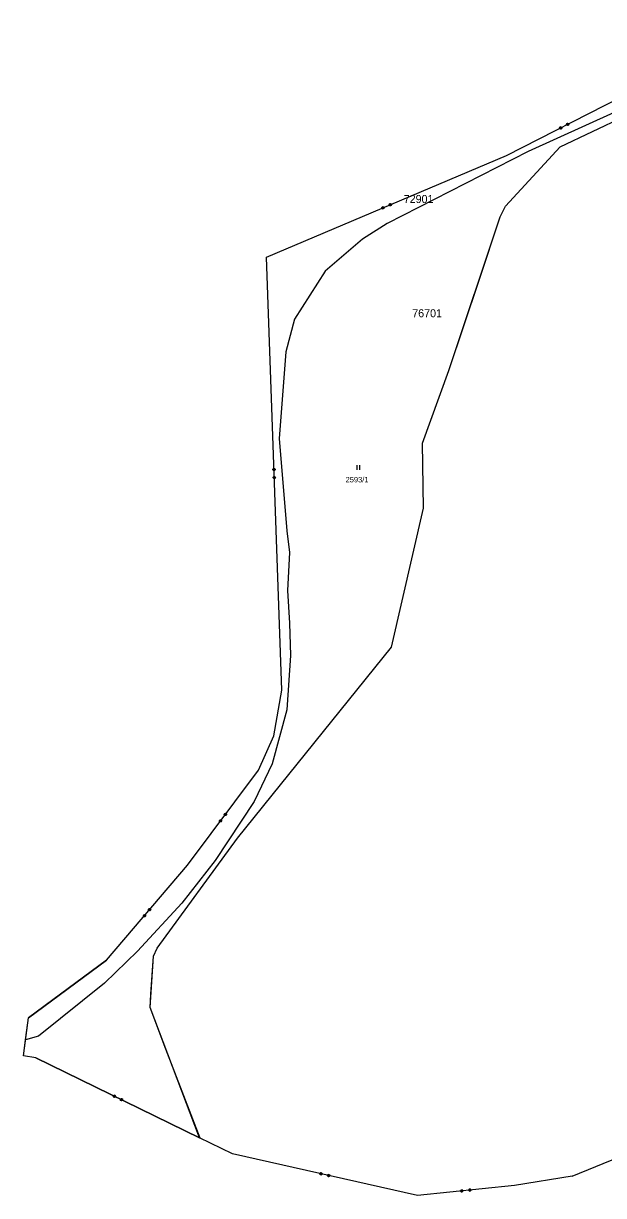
# Model space of a CAD drawing. Extents: x -760611 to -758411, y -1176479 to -1174807.
# Drawn here: x -760611.1 to -760429.8, y -1176478.9 to -1176112.8 of the extents above; entities that cross this region are included whole.
import ezdxf

# ---------------------------------------------------------------- set-up
doc = ezdxf.new("R2010")
doc.units = 0
for name, color, linetype in [('1', 7, 'Continuous'), ('11', 7, 'Continuous'), ('2', 7, 'Continuous'), ('3', 7, 'Continuous')]:
    doc.layers.add(name, color=color, linetype=linetype)

msp = doc.modelspace()

# ---------------------------------------------------------------- linework, layer by layer
at = {"layer": '1'}
for p, q in [((-760460.11, -1176154.07), (-760424.14, -1176135.79)), ((-760443.32, -1176151.33), (-760423.07, -1176141.77)), ((-760460.38, -1176169.87), (-760443.32, -1176151.33)), ((-760535.16, -1176185.8), (-760460.11, -1176154.07)), ((-760462.1, -1176173.26), (-760460.38, -1176169.87)), ((-760478.12, -1176221.24), (-760462.1, -1176173.26)), ((-760530.31, -1176321.04), (-760535.16, -1176185.8)), ((-760486.4, -1176243.86), (-760478.12, -1176221.24)), ((-760486.07, -1176264.19), (-760486.4, -1176243.86)), ((-760496.02, -1176307.61), (-760486.07, -1176264.19)), ((-760544.14, -1176367.23), (-760496.02, -1176307.61)), ((-760532.8, -1176335.28), (-760530.31, -1176321.04)), ((-760537.67, -1176346.05), (-760532.8, -1176335.28)), ((-760559.85, -1176375.71), (-760537.67, -1176346.05)), ((-760569.34, -1176401.64), (-760544.14, -1176367.23)), ((-760585.17, -1176405.4), (-760559.85, -1176375.71)), ((-760570.49, -1176404.12), (-760569.34, -1176401.64)), ((-760585.17, -1176405.4), (-760601.92, -1176417.76)), ((-760571.54, -1176420.09), (-760570.49, -1176404.12)), ((-760601.92, -1176417.76), (-760609.56, -1176423.39)), ((-760556.03, -1176460.82), (-760571.54, -1176420.09)), ((-760611.11, -1176435.21), (-760609.56, -1176423.39)), ((-760607.21, -1176435.9), (-760611.11, -1176435.21)), ((-760607.21, -1176435.9), (-760556.03, -1176460.82)), ((-760545.74, -1176465.83), (-760556.03, -1176460.82)), ((-760487.96, -1176478.86), (-760545.74, -1176465.83)), ((-760439.57, -1176472.8), (-760424.82, -1176466.77)), ((-760457.63, -1176475.7), (-760487.96, -1176478.86)), ((-760439.57, -1176472.8), (-760457.63, -1176475.7))]:
    msp.add_line(p, q, dxfattribs=at)
for points in [[(-760443.22, -1176145.13), (-760442.97, -1176145.21), (-760442.85, -1176145.45), (-760442.93, -1176145.71), (-760443.17, -1176145.83), (-760443.43, -1176145.75), (-760443.55, -1176145.51), (-760443.46, -1176145.25), (-760443.22, -1176145.13), (-760443.21, -1176145.17), (-760443.43, -1176145.28), (-760443.46, -1176145.39), (-760443.11, -1176145.2), (-760443, -1176145.24), (-760443.5, -1176145.49), (-760443.46, -1176145.56), (-760442.96, -1176145.31), (-760442.93, -1176145.38), (-760443.43, -1176145.64), (-760443.39, -1176145.71), (-760442.89, -1176145.45), (-760442.93, -1176145.56), (-760443.28, -1176145.74), (-760443.18, -1176145.78), (-760442.96, -1176145.67)], [(-760440.99, -1176144), (-760440.74, -1176144.08), (-760440.62, -1176144.32), (-760440.7, -1176144.58), (-760440.94, -1176144.7), (-760441.2, -1176144.62), (-760441.32, -1176144.37), (-760441.24, -1176144.12), (-760440.99, -1176144), (-760441, -1176144.05), (-760441.22, -1176144.16), (-760441.25, -1176144.26), (-760440.9, -1176144.08), (-760440.79, -1176144.12), (-760441.29, -1176144.37), (-760441.25, -1176144.44), (-760440.75, -1176144.19), (-760440.72, -1176144.26), (-760441.22, -1176144.51), (-760441.18, -1176144.58), (-760440.68, -1176144.33), (-760440.71, -1176144.44), (-760441.07, -1176144.62), (-760440.96, -1176144.65), (-760440.75, -1176144.55)], [(-760498.75, -1176170.06), (-760498.5, -1176170.16), (-760498.39, -1176170.41), (-760498.49, -1176170.66), (-760498.74, -1176170.76), (-760498.99, -1176170.66), (-760499.09, -1176170.41), (-760498.99, -1176170.16), (-760498.75, -1176170.06), (-760498.74, -1176170.1), (-760498.96, -1176170.19), (-760499, -1176170.3), (-760498.63, -1176170.14), (-760498.53, -1176170.18), (-760499.04, -1176170.4), (-760499.01, -1176170.47), (-760498.5, -1176170.26), (-760498.47, -1176170.33), (-760498.98, -1176170.55), (-760498.95, -1176170.62), (-760498.44, -1176170.4), (-760498.48, -1176170.51), (-760498.85, -1176170.66), (-760498.74, -1176170.71), (-760498.52, -1176170.61)], [(-760496.44, -1176169.08), (-760496.19, -1176169.18), (-760496.09, -1176169.43), (-760496.19, -1176169.68), (-760496.44, -1176169.79), (-760496.69, -1176169.69), (-760496.79, -1176169.44), (-760496.69, -1176169.19), (-760496.44, -1176169.08), (-760496.45, -1176169.13), (-760496.68, -1176169.23), (-760496.72, -1176169.33), (-760496.35, -1176169.17), (-760496.24, -1176169.22), (-760496.76, -1176169.44), (-760496.73, -1176169.51), (-760496.21, -1176169.29), (-760496.18, -1176169.36), (-760496.7, -1176169.58), (-760496.67, -1176169.66), (-760496.15, -1176169.44), (-760496.19, -1176169.54), (-760496.56, -1176169.7), (-760496.46, -1176169.74), (-760496.24, -1176169.65)], [(-760533.11, -1176252), (-760532.92, -1176251.81), (-760532.65, -1176251.8), (-760532.46, -1176251.98), (-760532.45, -1176252.25), (-760532.63, -1176252.45), (-760532.9, -1176252.46), (-760533.1, -1176252.27), (-760533.11, -1176252), (-760533.07, -1176252.03), (-760533.06, -1176252.27), (-760532.97, -1176252.35), (-760532.99, -1176251.95), (-760532.91, -1176251.87), (-760532.89, -1176252.42), (-760532.81, -1176252.42), (-760532.83, -1176251.86), (-760532.75, -1176251.86), (-760532.73, -1176252.42), (-760532.65, -1176252.42), (-760532.67, -1176251.86), (-760532.59, -1176251.93), (-760532.57, -1176252.33), (-760532.5, -1176252.25), (-760532.51, -1176252.01)], [(-760533.02, -1176254.5), (-760532.83, -1176254.3), (-760532.56, -1176254.29), (-760532.37, -1176254.48), (-760532.36, -1176254.75), (-760532.54, -1176254.94), (-760532.81, -1176254.95), (-760533.01, -1176254.77), (-760533.02, -1176254.5), (-760532.98, -1176254.51), (-760532.97, -1176254.75), (-760532.88, -1176254.83), (-760532.9, -1176254.43), (-760532.82, -1176254.34), (-760532.8, -1176254.9), (-760532.72, -1176254.9), (-760532.74, -1176254.34), (-760532.66, -1176254.34), (-760532.64, -1176254.9), (-760532.56, -1176254.89), (-760532.58, -1176254.34), (-760532.5, -1176254.41), (-760532.48, -1176254.81), (-760532.41, -1176254.73), (-760532.42, -1176254.49)], [(-760549.66, -1176361.55), (-760549.39, -1176361.51), (-760549.17, -1176361.67), (-760549.14, -1176361.93), (-760549.3, -1176362.15), (-760549.56, -1176362.19), (-760549.78, -1176362.03), (-760549.82, -1176361.76), (-760549.66, -1176361.55), (-760549.63, -1176361.58), (-760549.77, -1176361.77), (-760549.76, -1176361.88), (-760549.52, -1176361.56), (-760549.41, -1176361.55), (-760549.74, -1176361.99), (-760549.68, -1176362.04), (-760549.34, -1176361.59), (-760549.28, -1176361.64), (-760549.61, -1176362.09), (-760549.55, -1176362.14), (-760549.21, -1176361.69), (-760549.2, -1176361.8), (-760549.44, -1176362.12), (-760549.33, -1176362.1), (-760549.18, -1176361.91)], [(-760548.16, -1176359.54), (-760547.89, -1176359.5), (-760547.68, -1176359.67), (-760547.64, -1176359.93), (-760547.8, -1176360.15), (-760548.07, -1176360.19), (-760548.28, -1176360.03), (-760548.32, -1176359.76), (-760548.16, -1176359.54), (-760548.15, -1176359.59), (-760548.29, -1176359.78), (-760548.27, -1176359.9), (-760548.03, -1176359.57), (-760547.92, -1176359.56), (-760548.26, -1176360.01), (-760548.19, -1176360.06), (-760547.86, -1176359.61), (-760547.79, -1176359.65), (-760548.13, -1176360.1), (-760548.07, -1176360.15), (-760547.73, -1176359.7), (-760547.71, -1176359.81), (-760547.95, -1176360.13), (-760547.84, -1176360.12), (-760547.7, -1176359.93)], [(-760573.45, -1176391.16), (-760573.18, -1176391.14), (-760572.97, -1176391.32), (-760572.95, -1176391.58), (-760573.13, -1176391.79), (-760573.4, -1176391.81), (-760573.6, -1176391.64), (-760573.62, -1176391.37), (-760573.45, -1176391.16), (-760573.42, -1176391.2), (-760573.58, -1176391.38), (-760573.57, -1176391.49), (-760573.31, -1176391.19), (-760573.2, -1176391.18), (-760573.56, -1176391.6), (-760573.5, -1176391.66), (-760573.14, -1176391.23), (-760573.08, -1176391.28), (-760573.44, -1176391.71), (-760573.38, -1176391.76), (-760573.02, -1176391.33), (-760573.01, -1176391.45), (-760573.27, -1176391.75), (-760573.15, -1176391.74), (-760573, -1176391.56)], [(-760571.83, -1176389.26), (-760571.56, -1176389.24), (-760571.35, -1176389.41), (-760571.33, -1176389.68), (-760571.51, -1176389.89), (-760571.77, -1176389.91), (-760571.98, -1176389.73), (-760572, -1176389.46), (-760571.83, -1176389.26), (-760571.82, -1176389.31), (-760571.97, -1176389.49), (-760571.96, -1176389.6), (-760571.7, -1176389.3), (-760571.59, -1176389.29), (-760571.95, -1176389.72), (-760571.89, -1176389.77), (-760571.53, -1176389.34), (-760571.47, -1176389.39), (-760571.83, -1176389.82), (-760571.77, -1176389.87), (-760571.41, -1176389.45), (-760571.4, -1176389.56), (-760571.66, -1176389.86), (-760571.54, -1176389.85), (-760571.39, -1176389.67)], [(-760582.44, -1176447.6), (-760582.35, -1176447.86), (-760582.47, -1176448.1), (-760582.73, -1176448.19), (-760582.97, -1176448.07), (-760583.06, -1176447.82), (-760582.94, -1176447.57), (-760582.68, -1176447.49), (-760582.44, -1176447.6), (-760582.47, -1176447.64), (-760582.68, -1176447.53), (-760582.79, -1176447.57), (-760582.43, -1176447.74), (-760582.39, -1176447.85), (-760582.9, -1176447.6), (-760582.93, -1176447.68), (-760582.43, -1176447.92), (-760582.46, -1176447.99), (-760582.97, -1176447.75), (-760583, -1176447.82), (-760582.5, -1176448.07), (-760582.61, -1176448.1), (-760582.97, -1176447.93), (-760582.93, -1176448.03), (-760582.71, -1176448.14)], [(-760580.19, -1176448.7), (-760580.11, -1176448.95), (-760580.22, -1176449.2), (-760580.48, -1176449.28), (-760580.72, -1176449.16), (-760580.81, -1176448.91), (-760580.69, -1176448.67), (-760580.44, -1176448.58), (-760580.19, -1176448.7), (-760580.24, -1176448.72), (-760580.45, -1176448.62), (-760580.56, -1176448.65), (-760580.2, -1176448.83), (-760580.16, -1176448.94), (-760580.67, -1176448.69), (-760580.7, -1176448.76), (-760580.2, -1176449.01), (-760580.23, -1176449.08), (-760580.74, -1176448.83), (-760580.77, -1176448.91), (-760580.27, -1176449.15), (-760580.38, -1176449.19), (-760580.74, -1176449.01), (-760580.7, -1176449.12), (-760580.48, -1176449.22)], [(-760518.32, -1176472.34), (-760518.46, -1176472.12), (-760518.4, -1176471.85), (-760518.17, -1176471.71), (-760517.91, -1176471.77), (-760517.77, -1176472), (-760517.82, -1176472.26), (-760518.05, -1176472.4), (-760518.32, -1176472.34), (-760518.28, -1176472.31), (-760518.04, -1176472.36), (-760517.95, -1176472.3), (-760518.34, -1176472.21), (-760518.4, -1176472.12), (-760517.85, -1176472.24), (-760517.83, -1176472.16), (-760518.38, -1176472.04), (-760518.36, -1176471.96), (-760517.82, -1176472.09), (-760517.8, -1176472.01), (-760518.35, -1176471.89), (-760518.25, -1176471.82), (-760517.86, -1176471.91), (-760517.92, -1176471.82), (-760518.15, -1176471.76)], [(-760515.88, -1176472.89), (-760516.02, -1176472.67), (-760515.96, -1176472.4), (-760515.73, -1176472.26), (-760515.47, -1176472.32), (-760515.33, -1176472.54), (-760515.39, -1176472.81), (-760515.61, -1176472.95), (-760515.88, -1176472.89), (-760515.86, -1176472.86), (-760515.62, -1176472.91), (-760515.53, -1176472.85), (-760515.92, -1176472.76), (-760515.98, -1176472.66), (-760515.43, -1176472.79), (-760515.41, -1176472.71), (-760515.96, -1176472.59), (-760515.94, -1176472.51), (-760515.4, -1176472.63), (-760515.38, -1176472.55), (-760515.93, -1176472.43), (-760515.83, -1176472.37), (-760515.44, -1176472.46), (-760515.5, -1176472.36), (-760515.73, -1176472.31)], [(-760474.18, -1176477.75), (-760474.39, -1176477.58), (-760474.42, -1176477.31), (-760474.25, -1176477.1), (-760473.98, -1176477.07), (-760473.77, -1176477.24), (-760473.75, -1176477.51), (-760473.92, -1176477.72), (-760474.18, -1176477.75), (-760474.16, -1176477.7), (-760473.92, -1176477.68), (-760473.85, -1176477.59), (-760474.25, -1176477.63), (-760474.33, -1176477.56), (-760473.78, -1176477.5), (-760473.79, -1176477.42), (-760474.34, -1176477.48), (-760474.35, -1176477.4), (-760473.79, -1176477.34), (-760473.8, -1176477.26), (-760474.36, -1176477.32), (-760474.29, -1176477.23), (-760473.89, -1176477.19), (-760473.98, -1176477.12), (-760474.22, -1176477.15)], [(-760471.7, -1176477.49), (-760471.91, -1176477.32), (-760471.93, -1176477.05), (-760471.76, -1176476.84), (-760471.5, -1176476.81), (-760471.29, -1176476.98), (-760471.26, -1176477.25), (-760471.43, -1176477.46), (-760471.7, -1176477.49), (-760471.69, -1176477.45), (-760471.45, -1176477.42), (-760471.38, -1176477.33), (-760471.78, -1176477.38), (-760471.87, -1176477.3), (-760471.31, -1176477.25), (-760471.32, -1176477.17), (-760471.88, -1176477.22), (-760471.88, -1176477.15), (-760471.33, -1176477.09), (-760471.34, -1176477.01), (-760471.89, -1176477.07), (-760471.82, -1176476.98), (-760471.42, -1176476.94), (-760471.51, -1176476.87), (-760471.75, -1176476.89)]]:
    msp.add_lwpolyline(points, dxfattribs=at)
at = {"layer": '11'}
msp.add_line((-760606.43, -1176429.08), (-760610.45, -1176430.21), dxfattribs=at)
for points in [[(-760610.45, -1176430.21), (-760609.56, -1176423.39), (-760585.17, -1176405.4), (-760559.85, -1176375.71), (-760537.67, -1176346.05), (-760532.8, -1176335.28), (-760530.31, -1176321.04), (-760535.16, -1176185.8), (-760460.11, -1176154.07), (-760424.14, -1176135.79), (-760397.95, -1176122.89), (-760368.61, -1176112.84), (-760363.38, -1176119.64)], [(-760555.89, -1176460.89), (-760566.55, -1176433.11), (-760571.54, -1176420.09), (-760571.27, -1176415.93), (-760570.49, -1176404.12), (-760569.34, -1176401.64), (-760544.14, -1176367.23), (-760496.02, -1176307.61), (-760486.07, -1176264.19), (-760486.4, -1176243.86), (-760483.8, -1176236.76), (-760478.12, -1176221.24), (-760468.8, -1176193.32), (-760462.1, -1176173.26), (-760460.38, -1176169.87), (-760443.32, -1176151.33), (-760423.07, -1176141.77), (-760393.52, -1176134.03), (-760363.05, -1176128.35), (-760357.48, -1176127.31)], [(-760426.42, -1176140.6), (-760453.35, -1176152.8), (-760497.43, -1176175.27), (-760505.15, -1176180.21), (-760516.77, -1176190.16), (-760526.35, -1176205.23), (-760529.06, -1176215.35), (-760531.21, -1176242.42), (-760528.72, -1176271.27), (-760527.98, -1176278.06), (-760528.6, -1176289.91), (-760527.92, -1176300.09), (-760527.67, -1176310.26), (-760528.79, -1176327.18), (-760533.32, -1176344.04), (-760539.02, -1176355.79), (-760551.21, -1176374.2), (-760561.62, -1176387.56), (-760575.44, -1176402.55), (-760585.79, -1176412.53), (-760606.43, -1176429.08)], [(-760555.89, -1176460.89), (-760556.03, -1176460.82), (-760607.21, -1176435.9), (-760611.11, -1176435.21), (-760610.45, -1176430.21)]]:
    msp.add_lwpolyline(points, dxfattribs=at)
at = {"layer": '3'}
for p, q in [((-760506.91, -1176250.78), (-760506.91, -1176252.28)), ((-760505.91, -1176252.28), (-760505.91, -1176250.78))]:
    msp.add_line(p, q, dxfattribs=at)

# ---------------------------------------------------------------- texts
at = {"layer": '11'}
for s, p in [('72901', (-760492.23, -1176168.91)), ('76701', (-760489.57, -1176204.59))]:
    msp.add_text(s, height=2.5, dxfattribs=at).set_placement(p)
at = {"layer": '2'}
msp.add_text('2593/1', height=1.7, dxfattribs=at).set_placement((-760510.42, -1176256.15))

doc.saveas('drawing.dxf')
